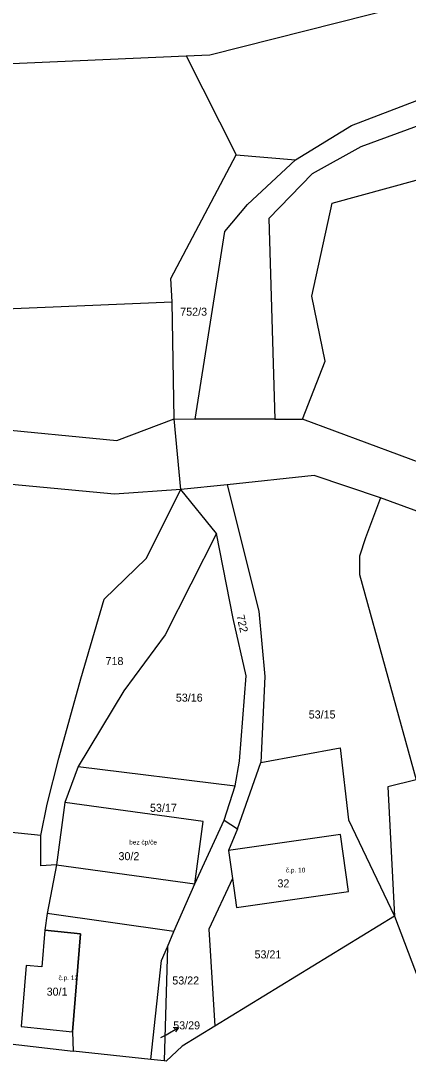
# Model space of a CAD drawing. Extents: x -887272 to -880188, y -1026687 to -1021896.
# Drawn here: x -883058.7 to -882976.6, y -1024083.7 to -1023862.8 of the extents above; entities that cross this region are included whole.
import ezdxf

# ---------------------------------------------------------------- set-up
doc = ezdxf.new("R2010")
doc.units = 0
for name, color, linetype in [('Definiční body', 7, 'Continuous'), ('Hranice parcel', 7, 'Continuous'), ('Parcelní čísla', 7, 'Continuous'), ('Polygon budovy', 7, 'Continuous'), ('Pop  PČ popisy', 7, 'Continuous'), ('Vnitřní kresba', 7, 'Continuous')]:
    doc.layers.add(name, color=color, linetype=linetype)

msp = doc.modelspace()

# ---------------------------------------------------------------- linework, layer by layer
at = {"layer": 'Hranice parcel'}
for p, q in [((-883023.64, -1023870.22), (-883013.08, -1023891.28)), ((-883013.08, -1023891.28), (-883000.47, -1023892.28)), ((-883006.13, -1023904.79), (-883004.83, -1023947.42)), ((-883021.73, -1023947.42), (-883015.44, -1023907.54)), ((-883178.1, -1023929.02), (-883026.61, -1023922.44)), ((-883026.2, -1023947.29), (-883026.61, -1023922.44)), ((-883038.36, -1023951.95), (-883026.2, -1023947.29)), ((-883026.2, -1023947.29), (-883021.73, -1023947.42)), ((-883024.78, -1023962.34), (-883026.2, -1023947.29)), ((-883004.83, -1023947.42), (-883021.73, -1023947.42)), ((-883004.83, -1023947.42), (-882999.02, -1023947.42)), ((-882947.44, -1023966.47), (-882999.02, -1023947.42)), ((-883014.98, -1023961.36), (-883024.78, -1023962.34)), ((-883017.26, -1023971.66), (-883024.78, -1023962.34)), ((-882986.9, -1023980.38), (-882974.9, -1024023.97)), ((-883007.84, -1024020.32), (-882990.97, -1024017.19)), ((-883046.55, -1024021.12), (-883049.37, -1024028.83)), ((-883046.55, -1024021.12), (-883013.3, -1024025.24)), ((-883012.76, -1024034.42), (-883007.84, -1024020.32)), ((-883015.61, -1024032.54), (-883013.3, -1024025.24)), ((-882974.9, -1024023.97), (-882980.91, -1024025.5)), ((-882980.91, -1024025.5), (-882979.5, -1024052.93)), ((-883049.37, -1024028.83), (-883051.19, -1024042.07)), ((-883021.84, -1024046.1), (-883015.61, -1024032.54)), ((-883015.61, -1024032.54), (-883012.76, -1024034.42)), ((-883012.76, -1024034.42), (-883014.66, -1024038.99)), ((-883014.66, -1024038.99), (-883013.83, -1024044.93)), ((-883051.19, -1024042.07), (-883053.13, -1024052.37)), ((-883013.83, -1024044.93), (-883018.87, -1024055.68)), ((-883026.3, -1024056.19), (-883021.84, -1024046.1)), ((-883026.3, -1024056.19), (-883053.13, -1024052.37)), ((-882979.5, -1024052.93), (-883017.57, -1024076.27)), ((-882979.5, -1024052.93), (-882970.63, -1024076.39)), ((-883027.64, -1024059.42), (-883026.3, -1024056.19)), ((-883018.87, -1024055.68), (-883017.57, -1024076.27)), ((-883027.64, -1024059.42), (-883028.33, -1024083.69)), ((-883031.12, -1024083.39), (-883047.64, -1024081.6)), ((-883028.33, -1024083.69), (-883031.12, -1024083.39))]:
    msp.add_line(p, q, dxfattribs=at)
for points in [[(-883023.64, -1023870.22), (-883018.61, -1023870), (-882937.74, -1023849.5), (-882908.79, -1023838.53), (-882874.84, -1023816.57)], [(-883000.47, -1023892.28), (-882988.57, -1023885.01), (-882974.72, -1023879.72), (-882947.73, -1023872.42), (-882916.42, -1023865.07)], [(-883093.7, -1023874.44), (-883086.38, -1023873.01), (-883023.64, -1023870.22)], [(-882922.29, -1023871.33), (-882946.52, -1023877.04), (-882973.33, -1023884.65), (-882986.6, -1023889.58), (-882996.92, -1023895.29), (-883006.13, -1023904.79)], [(-882999.02, -1023947.42), (-882994.2, -1023935.08), (-882996.98, -1023921.26), (-882992.7, -1023901.52), (-882945.96, -1023888.71)], [(-883026.61, -1023922.44), (-883026.88, -1023917.54), (-883013.08, -1023891.28)], [(-883015.44, -1023907.54), (-883010.67, -1023901.8), (-883000.47, -1023892.28)], [(-883188.08, -1023937.71), (-883148.98, -1023941.16), (-883038.36, -1023951.95)], [(-883024.78, -1023962.34), (-883038.88, -1023963.34), (-883149.62, -1023952.88), (-883229.75, -1023945.68)], [(-882982.44, -1023964.11), (-882996.5, -1023959.36), (-883014.98, -1023961.36)], [(-883014.98, -1023961.36), (-883008.22, -1023988.2), (-883006.98, -1024002.04), (-883007.84, -1024020.32)], [(-883054.46, -1024035.79), (-883053.12, -1024029.14), (-883050.64, -1024019.36), (-883046.02, -1024002.54), (-883041.08, -1023985.64), (-883032.14, -1023976.98), (-883024.78, -1023962.34)], [(-882982.44, -1023964.11), (-882985.61, -1023972.61), (-882986.9, -1023976.5), (-882986.9, -1023980.38)], [(-882957.52, -1023973.24), (-882960.99, -1023971.96), (-882982.44, -1023964.11)], [(-883017.26, -1023971.66), (-883028.08, -1023993.18), (-883036.86, -1024005.08), (-883046.55, -1024021.12)], [(-883013.3, -1024025.24), (-883012.38, -1024020.04), (-883010.94, -1024001.88), (-883013.66, -1023989.7), (-883017.26, -1023971.66)], [(-882990.97, -1024017.19), (-882989.22, -1024032.47), (-882979.5, -1024052.93)], [(-883021.84, -1024046.1), (-883020.04, -1024032.82), (-883049.37, -1024028.83)], [(-883054.46, -1024035.79), (-883074.51, -1024033.76), (-883078.86, -1024075.42)], [(-883051.19, -1024042.07), (-883054.48, -1024042.28), (-883054.46, -1024035.79)], [(-883013.83, -1024044.93), (-883012.97, -1024051.07), (-882989.21, -1024047.72), (-882990.9, -1024035.63), (-883014.66, -1024038.99)], [(-883053.13, -1024052.37), (-883053.65, -1024055.9), (-883054.3, -1024063.7), (-883057.6, -1024063.4), (-883058.62, -1024076.34), (-883047.78, -1024077.52), (-883047.64, -1024081.6)], [(-883031.12, -1024083.39), (-883028.86, -1024062.36), (-883027.64, -1024059.42)], [(-883078.86, -1024075.42), (-883067.68, -1024079.26), (-883047.64, -1024081.6)], [(-883017.57, -1024076.27), (-883024.54, -1024080.54), (-883027.89, -1024083.74), (-883028.33, -1024083.69)]]:
    msp.add_lwpolyline(points, dxfattribs=at)
at = {"layer": 'Polygon budovy'}
for points in [[(-883021.84, -1024046.1), (-883020.04, -1024032.82), (-883049.37, -1024028.83), (-883051.19, -1024042.07)], [(-883014.66, -1024038.99), (-883013.83, -1024044.93), (-883012.97, -1024051.07), (-882989.21, -1024047.72), (-882990.9, -1024035.63)], [(-883058.62, -1024076.34), (-883047.78, -1024077.52), (-883046.06, -1024056.7), (-883053.65, -1024055.9), (-883054.3, -1024063.7), (-883057.6, -1024063.4)]]:
    msp.add_lwpolyline(points, close=True, dxfattribs=at)
at = {"layer": 'Pop  PČ popisy'}
for p, q in [((-883027.9, -1024078.11), (-883025.3, -1024076.61)), ((-883025.3, -1024076.61), (-883026.42, -1024076.68)), ((-883025.3, -1024076.61), (-883025.92, -1024077.54)), ((-883029, -1024078.74), (-883027.9, -1024078.11))]:
    msp.add_line(p, q, dxfattribs=at)
at = {"layer": 'Vnitřní kresba'}
for p, q in [((-883051.19, -1024042.07), (-883021.84, -1024046.1)), ((-883053.65, -1024055.9), (-883046.06, -1024056.7)), ((-883046.06, -1024056.7), (-883047.78, -1024077.52))]:
    msp.add_line(p, q, dxfattribs=at)

# ---------------------------------------------------------------- texts
at = {"layer": 'Definiční body'}
for s, p in [('bez čp/če', (-883035.75, -1024037.73)), ('č.p. 10', (-883002.53, -1024043.66)), ('č.p. 12', (-883050.73, -1024066.53))]:
    msp.add_text(s, height=1, dxfattribs=at).set_placement(p)
at = {"layer": 'Parcelní čísla'}
for s, p in [('752/3', (-883024.92, -1023925.42)), ('718', (-883040.76, -1023999.61)), ('53/16', (-883025.85, -1024007.38)), ('53/15', (-882997.67, -1024010.96)), ('53/17', (-883031.33, -1024030.78)), ('30/2', (-883038.01, -1024041.05)), ('32', (-883004.3, -1024046.83)), ('53/21', (-883009.16, -1024061.91)), ('53/22', (-883026.6, -1024067.45)), ('30/1', (-883053.25, -1024069.82)), ('53/29', (-883026.4, -1024076.98))]:
    msp.add_text(s, height=1.7, dxfattribs=at).set_placement(p)
msp.add_text('722', height=1.7, rotation=283, dxfattribs=at).set_placement((-883013.01, -1023989.15))

doc.saveas('drawing.dxf')
